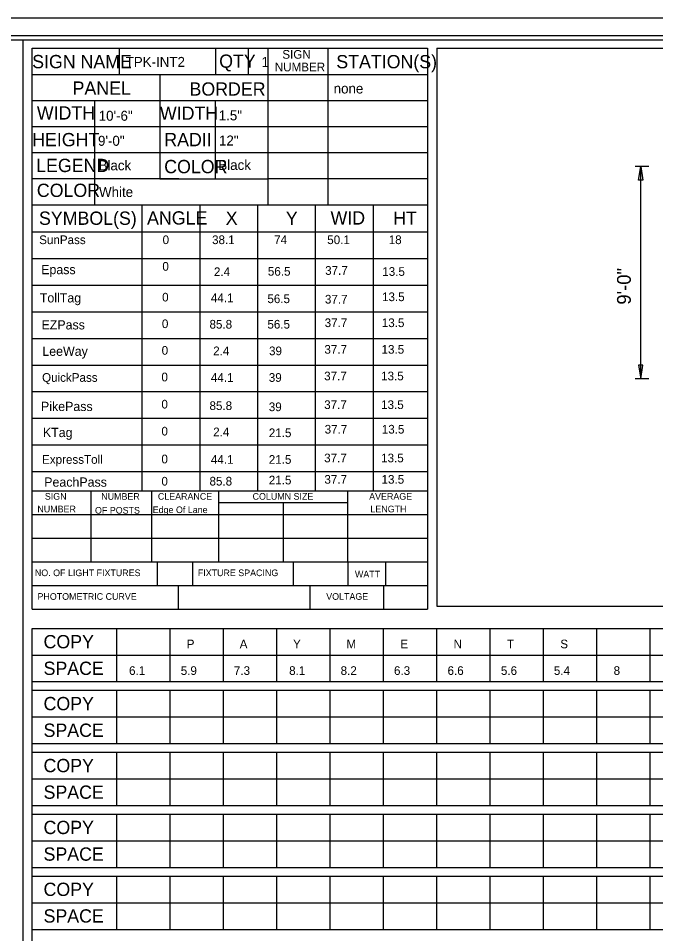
# Model space of a CAD drawing. Extents: x 17890459 to 17890580, y 17897938 to 17898017.
# Drawn here: x 17890519.38 to 17890546.34, y 17897978.61 to 17898017.37 of the extents above; entities that cross this region are included whole.
import ezdxf

# ---------------------------------------------------------------- set-up
doc = ezdxf.new("R2010")
doc.units = 0
for name, color, linetype in [('GSDims', 7, 'Continuous'), ('GSSign', 7, 'Continuous'), ('PlotBorder_dp', 7, 'Continuous'), ('SheetBorder_dp', 7, 'Continuous'), ('SheetLinesMisc2_dp', 7, 'Continuous'), ('TextMinor', 7, 'Continuous')]:
    doc.layers.add(name, color=color, linetype=linetype)

msp = doc.modelspace()

# ---------------------------------------------------------------- linework, layer by layer
at = {"layer": 'GSDims'}
for p, q in [((17890546.059, 17898011.097), (17890545.475, 17898011.097)), ((17890546.059, 17898011.097), (17890545.475, 17898011.097)), ((17890546.059, 17898011.097), (17890545.475, 17898011.097)), ((17890546.059, 17898011.097), (17890545.475, 17898011.097)), ((17890546.059, 17898011.097), (17890545.475, 17898011.097)), ((17890545.709, 17898002.097), (17890545.709, 17898011.097)), ((17890546.059, 17898002.097), (17890545.475, 17898002.097)), ((17890546.059, 17898002.097), (17890545.475, 17898002.097)), ((17890546.059, 17898002.097), (17890545.475, 17898002.097)), ((17890546.059, 17898002.097), (17890545.475, 17898002.097)), ((17890546.059, 17898002.097), (17890545.475, 17898002.097))]:
    msp.add_line(p, q, dxfattribs=at)
for points in [[(17890545.709, 17898011.097), (17890545.806, 17898010.514), (17890545.612, 17898010.514)], [(17890545.709, 17898002.097), (17890545.806, 17898002.681), (17890545.612, 17898002.681)]]:
    msp.add_lwpolyline(points, close=True, dxfattribs=at)
at = {"layer": 'PlotBorder_dp'}
msp.add_lwpolyline([(17890458.908, 17897939.544), (17890580.045, 17897939.544), (17890580.045, 17898017.365), (17890458.908, 17898017.365)], close=True, dxfattribs=at)
at = {"layer": 'SheetBorder_dp'}
msp.add_line((17890462.946, 17898016.631), (17890576.007, 17898016.631), dxfattribs=at)
at = {"layer": 'SheetLinesMisc2_dp'}
for p, q in [((17890463.151, 17898016.456), (17890575.98, 17898016.456)), ((17890463.151, 17898016.456), (17890575.98, 17898016.456)), ((17890519.566, 17898016.456), (17890519.566, 17897946.221)), ((17890519.963, 17897992.352), (17890519.963, 17898016.096)), ((17890519.963, 17898016.096), (17890536.692, 17898016.096)), ((17890523.65, 17898016.096), (17890523.65, 17898014.992)), ((17890527.717, 17898016.096), (17890527.717, 17898014.992)), ((17890529.106, 17898016.096), (17890529.106, 17898014.992)), ((17890529.934, 17898016.096), (17890529.934, 17898009.472)), ((17890532.479, 17898016.096), (17890532.479, 17898009.472)), ((17890536.692, 17898016.096), (17890536.692, 17897992.352)), ((17890537.078, 17898016.097), (17890575.452, 17898016.097)), ((17890537.078, 17898016.097), (17890537.078, 17897992.48)), ((17890519.963, 17898014.992), (17890536.692, 17898014.992)), ((17890525.369, 17898014.992), (17890525.369, 17898010.564)), ((17890519.963, 17898013.888), (17890536.692, 17898013.888)), ((17890522.606, 17898013.888), (17890522.606, 17898009.472)), ((17890527.702, 17898013.876), (17890527.702, 17898010.564)), ((17890519.963, 17898012.784), (17890536.692, 17898012.784)), ((17890519.963, 17898011.68), (17890536.692, 17898011.68)), ((17890519.963, 17898010.576), (17890526.167, 17898010.576)), ((17890525.369, 17898010.564), (17890529.934, 17898010.564)), ((17890529.934, 17898010.576), (17890536.692, 17898010.576)), ((17890519.963, 17898009.472), (17890536.692, 17898009.472)), ((17890524.608, 17898009.45), (17890524.608, 17897997.36)), ((17890527.053, 17898009.45), (17890527.053, 17897997.36)), ((17890529.497, 17898009.45), (17890529.497, 17897997.36)), ((17890531.942, 17898009.45), (17890531.942, 17897997.36)), ((17890534.386, 17898009.45), (17890534.386, 17897997.36)), ((17890519.966, 17898008.323), (17890536.692, 17898008.323)), ((17890519.966, 17898007.195), (17890536.692, 17898007.195)), ((17890519.966, 17898006.068), (17890536.692, 17898006.068)), ((17890519.966, 17898004.941), (17890536.692, 17898004.941)), ((17890519.966, 17898003.813), (17890536.692, 17898003.813)), ((17890519.966, 17898002.686), (17890536.692, 17898002.686)), ((17890519.966, 17898001.558), (17890536.692, 17898001.558)), ((17890519.966, 17898000.431), (17890536.692, 17898000.431)), ((17890519.966, 17897999.304), (17890536.692, 17897999.304)), ((17890519.966, 17897998.176), (17890536.692, 17897998.176)), ((17890519.963, 17897997.36), (17890536.692, 17897997.36)), ((17890522.445, 17897997.36), (17890522.445, 17897994.355)), ((17890525.011, 17897997.36), (17890525.011, 17897994.355)), ((17890527.844, 17897997.36), (17890527.844, 17897994.355)), ((17890533.3, 17897997.36), (17890533.3, 17897994.355)), ((17890527.844, 17897996.87), (17890533.296, 17897996.87)), ((17890530.583, 17897996.87), (17890530.583, 17897994.355)), ((17890519.963, 17897996.358), (17890536.692, 17897996.358)), ((17890519.963, 17897995.357), (17890536.692, 17897995.357)), ((17890519.963, 17897994.355), (17890536.692, 17897994.355)), ((17890525.256, 17897994.355), (17890525.256, 17897993.354)), ((17890526.751, 17897994.355), (17890526.751, 17897993.354)), ((17890531.007, 17897994.355), (17890531.007, 17897993.354)), ((17890533.322, 17897994.355), (17890533.322, 17897993.354)), ((17890534.919, 17897994.355), (17890534.919, 17897993.354)), ((17890519.963, 17897993.354), (17890536.692, 17897993.354)), ((17890526.134, 17897993.354), (17890526.134, 17897992.352)), ((17890531.716, 17897993.354), (17890531.716, 17897992.352)), ((17890534.822, 17897993.354), (17890534.822, 17897992.352)), ((17890519.963, 17897992.352), (17890536.692, 17897992.352)), ((17890537.078, 17897992.48), (17890575.452, 17897992.48)), ((17890519.957, 17897991.536), (17890575.447, 17897991.536)), ((17890519.957, 17897947.331), (17890519.957, 17897991.536)), ((17890523.529, 17897991.536), (17890523.529, 17897989.281)), ((17890525.787, 17897991.536), (17890525.787, 17897989.281)), ((17890528.044, 17897991.536), (17890528.044, 17897989.281)), ((17890530.301, 17897991.536), (17890530.301, 17897989.281)), ((17890532.558, 17897991.536), (17890532.558, 17897989.281)), ((17890534.815, 17897991.536), (17890534.815, 17897989.281)), ((17890537.073, 17897991.536), (17890537.073, 17897989.281)), ((17890539.33, 17897991.536), (17890539.33, 17897989.281)), ((17890541.587, 17897991.536), (17890541.587, 17897989.281)), ((17890543.844, 17897991.536), (17890543.844, 17897989.281)), ((17890546.102, 17897991.536), (17890546.102, 17897989.281)), ((17890519.957, 17897990.408), (17890575.447, 17897990.408)), ((17890519.957, 17897989.281), (17890575.447, 17897989.281)), ((17890519.957, 17897988.914), (17890575.447, 17897988.914)), ((17890523.529, 17897988.914), (17890523.529, 17897986.659)), ((17890525.787, 17897988.914), (17890525.787, 17897986.659)), ((17890528.044, 17897988.914), (17890528.044, 17897986.659)), ((17890530.301, 17897988.914), (17890530.301, 17897986.659)), ((17890532.558, 17897988.914), (17890532.558, 17897986.659)), ((17890534.815, 17897988.914), (17890534.815, 17897986.659)), ((17890537.073, 17897988.914), (17890537.073, 17897986.659)), ((17890539.33, 17897988.914), (17890539.33, 17897986.659)), ((17890541.587, 17897988.914), (17890541.587, 17897986.659)), ((17890543.844, 17897988.914), (17890543.844, 17897986.659)), ((17890546.102, 17897988.914), (17890546.102, 17897986.659)), ((17890519.957, 17897987.786), (17890575.447, 17897987.786)), ((17890519.957, 17897986.659), (17890575.447, 17897986.659)), ((17890519.957, 17897986.291), (17890575.447, 17897986.291)), ((17890523.529, 17897986.291), (17890523.529, 17897984.037)), ((17890525.787, 17897986.291), (17890525.787, 17897984.037)), ((17890528.044, 17897986.291), (17890528.044, 17897984.037)), ((17890530.301, 17897986.291), (17890530.301, 17897984.037)), ((17890532.558, 17897986.291), (17890532.558, 17897984.037)), ((17890534.815, 17897986.291), (17890534.815, 17897984.037)), ((17890537.073, 17897986.291), (17890537.073, 17897984.037)), ((17890539.33, 17897986.291), (17890539.33, 17897984.037)), ((17890541.587, 17897986.291), (17890541.587, 17897984.037)), ((17890543.844, 17897986.291), (17890543.844, 17897984.037)), ((17890546.102, 17897986.291), (17890546.102, 17897984.037)), ((17890519.957, 17897985.165), (17890575.447, 17897985.165)), ((17890519.957, 17897984.037), (17890575.447, 17897984.037)), ((17890519.957, 17897983.669), (17890575.447, 17897983.669)), ((17890523.529, 17897983.669), (17890523.529, 17897981.415)), ((17890525.787, 17897983.669), (17890525.787, 17897981.415)), ((17890528.044, 17897983.669), (17890528.044, 17897981.415)), ((17890530.301, 17897983.669), (17890530.301, 17897981.415)), ((17890532.558, 17897983.669), (17890532.558, 17897981.415)), ((17890534.815, 17897983.669), (17890534.815, 17897981.415)), ((17890537.073, 17897983.669), (17890537.073, 17897981.415)), ((17890539.33, 17897983.669), (17890539.33, 17897981.415)), ((17890541.587, 17897983.669), (17890541.587, 17897981.415)), ((17890543.844, 17897983.669), (17890543.844, 17897981.415)), ((17890546.102, 17897983.669), (17890546.102, 17897981.415)), ((17890519.957, 17897982.543), (17890575.447, 17897982.543)), ((17890519.957, 17897981.415), (17890575.447, 17897981.415)), ((17890519.957, 17897981.048), (17890575.447, 17897981.048)), ((17890523.529, 17897981.048), (17890523.529, 17897978.794)), ((17890525.787, 17897981.048), (17890525.787, 17897978.794)), ((17890528.044, 17897981.048), (17890528.044, 17897978.794)), ((17890530.301, 17897981.048), (17890530.301, 17897978.794)), ((17890532.558, 17897981.048), (17890532.558, 17897978.794)), ((17890534.815, 17897981.048), (17890534.815, 17897978.794)), ((17890537.073, 17897981.048), (17890537.073, 17897978.794)), ((17890539.33, 17897981.048), (17890539.33, 17897978.794)), ((17890541.587, 17897981.048), (17890541.587, 17897978.794)), ((17890543.844, 17897981.048), (17890543.844, 17897978.794)), ((17890546.102, 17897981.048), (17890546.102, 17897978.794)), ((17890519.957, 17897979.92), (17890575.447, 17897979.921)), ((17890519.957, 17897978.794), (17890575.447, 17897978.794))]:
    msp.add_line(p, q, dxfattribs=at)

# ---------------------------------------------------------------- texts
at = {"layer": 'GSDims'}
msp.add_text('9\'-0"', height=0.5833, rotation=90, dxfattribs=at).set_placement((17890545.292, 17898005.242))
at = {"layer": 'GSSign'}
for s, height, p in [('TPK-INT2', 0.4218, (17890523.919, 17898015.308)), ('1', 0.422, (17890529.666, 17898015.307)), ('none', 0.4218, (17890532.719, 17898014.182)), ('10\'-6"', 0.4218, (17890522.778, 17898013.028)), ('1.5"', 0.4218, (17890527.857, 17898013.044)), ('9\'-0"', 0.4218, (17890522.749, 17898011.968)), ('12"', 0.4218, (17890527.868, 17898011.98)), ('Black', 0.4218, (17890522.773, 17898010.928)), ('Black', 0.4218, (17890527.84, 17898010.945)), ('White', 0.4218, (17890522.792, 17898009.8)), ('SunPass', 0.3676, (17890520.26, 17898007.805)), ('0', 0.368, (17890525.482, 17898007.805)), ('38.1', 0.3676, (17890527.575, 17898007.805)), ('74', 0.3676, (17890530.2, 17898007.805)), ('50.1', 0.3676, (17890532.448, 17898007.805)), ('18', 0.3676, (17890535.049, 17898007.805)), ('Epass', 0.3921, (17890520.345, 17898006.532)), ('0', 0.368, (17890525.472, 17898006.678)), ('37.7', 0.3676, (17890532.359, 17898006.504)), ('2.4', 0.3676, (17890527.652, 17898006.451)), ('56.5', 0.3676, (17890529.936, 17898006.468)), ('13.5', 0.3676, (17890534.776, 17898006.461)), ('TollTag', 0.3921, (17890520.287, 17898005.335)), ('0', 0.368, (17890525.462, 17898005.376)), ('44.1', 0.3676, (17890527.524, 17898005.347)), ('13.5', 0.3676, (17890534.766, 17898005.391)), ('56.5', 0.3676, (17890529.916, 17898005.307)), ('37.7', 0.3676, (17890532.349, 17898005.288)), ('EZPass', 0.3921, (17890520.358, 17898004.193)), ('0', 0.368, (17890525.452, 17898004.249)), ('85.8', 0.3676, (17890527.466, 17898004.228)), ('56.5', 0.3676, (17890529.916, 17898004.228)), ('37.7', 0.3676, (17890532.339, 17898004.292)), ('13.5', 0.3676, (17890534.756, 17898004.292)), ('LeeWay', 0.3921, (17890520.393, 17898003.074)), ('0', 0.368, (17890525.442, 17898003.122)), ('2.4', 0.3676, (17890527.622, 17898003.101)), ('39', 0.3676, (17890529.985, 17898003.101)), ('37.7', 0.3676, (17890532.329, 17898003.165)), ('13.5', 0.3676, (17890534.746, 17898003.165)), ('QuickPass', 0.3676, (17890520.382, 17898001.975)), ('0', 0.368, (17890525.432, 17898001.994)), ('44.1', 0.3676, (17890527.524, 17898001.974)), ('39', 0.3676, (17890529.975, 17898001.974)), ('37.7', 0.3676, (17890532.318, 17898002.038)), ('13.5', 0.3676, (17890534.727, 17898002.038)), ('PikePass', 0.3921, (17890520.336, 17898000.738)), ('0', 0.368, (17890525.432, 17898000.844)), ('85.8', 0.3676, (17890527.466, 17898000.781)), ('39', 0.3676, (17890529.975, 17898000.733)), ('37.7', 0.3676, (17890532.318, 17898000.823)), ('13.5', 0.3676, (17890534.727, 17898000.823)), ('KTag', 0.3921, (17890520.417, 17897999.635)), ('0', 0.368, (17890525.432, 17897999.702)), ('2.4', 0.3676, (17890527.622, 17897999.669)), ('21.5', 0.3676, (17890529.975, 17897999.632)), ('37.7', 0.3676, (17890532.339, 17897999.783)), ('13.5', 0.3676, (17890534.756, 17897999.783)), ('ExpressToll', 0.36762, (17890520.382, 17897998.504)), ('0', 0.368, (17890525.432, 17897998.523)), ('44.1', 0.3676, (17890527.524, 17897998.503)), ('21.5', 0.3676, (17890529.975, 17897998.503)), ('37.7', 0.3676, (17890532.318, 17897998.567)), ('13.5', 0.3676, (17890534.727, 17897998.567)), ('PeachPass', 0.3921, (17890520.473, 17897997.534)), ('0', 0.368, (17890525.432, 17897997.582)), ('85.8', 0.3676, (17890527.466, 17897997.584)), ('21.5', 0.3676, (17890529.975, 17897997.632)), ('37.7', 0.3676, (17890532.329, 17897997.661)), ('13.5', 0.3676, (17890534.746, 17897997.661)), ('P', 0.368, (17890526.503, 17897990.692)), ('A', 0.368, (17890528.744, 17897990.692)), ('Y', 0.368, (17890531.001, 17897990.692)), ('M', 0.368, (17890533.259, 17897990.692)), ('E', 0.368, (17890535.543, 17897990.692)), ('N', 0.368, (17890537.792, 17897990.692)), ('T', 0.368, (17890540.05, 17897990.692)), ('S', 0.368, (17890542.308, 17897990.692)), ('6.1', 0.3676, (17890524.062, 17897989.565)), ('5.9', 0.3676, (17890526.249, 17897989.565)), ('7.3', 0.3676, (17890528.498, 17897989.565)), ('8.1', 0.3676, (17890530.835, 17897989.565)), ('8.2', 0.3676, (17890533.014, 17897989.565)), ('6.3', 0.3676, (17890535.272, 17897989.565)), ('6.6', 0.3676, (17890537.538, 17897989.565)), ('5.6', 0.3676, (17890539.796, 17897989.565)), ('5.4', 0.3676, (17890542.036, 17897989.565)), ('8', 0.368, (17890544.565, 17897989.565))]:
    msp.add_text(s, height=height, dxfattribs=at).set_placement(p)
at = {"layer": 'TextMinor'}
for s, height, p in [('SIGN NAME', 0.5624, (17890519.963, 17898015.251)), ('QTY', 0.5624, (17890527.877, 17898015.27)), ('SIGN', 0.3676, (17890530.548, 17898015.654)), ('STATION(S)', 0.5624, (17890532.831, 17898015.248)), ('NUMBER', 0.3676, (17890530.228, 17898015.119)), ('PANEL', 0.5624, (17890521.673, 17898014.129)), ('BORDER', 0.5624, (17890526.62, 17898014.091)), ('WIDTH', 0.5624, (17890520.161, 17898013.079)), ('WIDTH', 0.5624, (17890525.369, 17898013.067)), ('HEIGHT', 0.5624, (17890519.963, 17898011.947)), ('RADII', 0.5624, (17890525.554, 17898011.949)), ('LEGEND', 0.5624, (17890520.132, 17898010.855)), ('COLOR', 0.5624, (17890525.55, 17898010.807)), ('COLOR', 0.5624, (17890520.161, 17898009.801)), ('SYMBOL(S)', 0.5624, (17890520.251, 17898008.621)), ('ANGLE', 0.5624, (17890524.824, 17898008.633)), ('X', 0.562, (17890528.153, 17898008.621)), ('Y', 0.562, (17890530.695, 17898008.621)), ('WID', 0.5624, (17890532.587, 17898008.633)), ('HT', 0.5624, (17890535.237, 17898008.622)), ('SIGN', 0.2812, (17890520.499, 17897996.984)), ('NUMBER', 0.2812, (17890522.886, 17897996.981)), ('CLEARANCE', 0.2812, (17890525.281, 17897996.983)), ('COLUMN SIZE', 0.28123, (17890529.289, 17897996.983)), ('AVERAGE', 0.2812, (17890534.221, 17897996.983)), ('NUMBER', 0.2812, (17890520.184, 17897996.449)), ('OF POSTS', 0.2812, (17890522.621, 17897996.396)), ('Edge Of Lane', 0.28123, (17890525.064, 17897996.417)), ('LENGTH', 0.2812, (17890534.275, 17897996.449)), ('NO. OF LIGHT FIXTURES', 0.28114, (17890520.078, 17897993.748)), ('FIXTURE SPACING', 0.28114, (17890526.971, 17897993.748)), ('WATT', 0.2811, (17890533.62, 17897993.692)), ('PHOTOMETRIC CURVE', 0.28114, (17890520.188, 17897992.746)), ('VOLTAGE', 0.2811, (17890532.405, 17897992.746)), ('COPY', 0.5625, (17890520.444, 17897990.692)), ('SPACE', 0.5625, (17890520.444, 17897989.565)), ('COPY', 0.5625, (17890520.444, 17897988.071)), ('SPACE', 0.5625, (17890520.444, 17897986.943)), ('COPY', 0.5625, (17890520.444, 17897985.448)), ('SPACE', 0.5625, (17890520.444, 17897984.321)), ('COPY', 0.5625, (17890520.444, 17897982.827)), ('SPACE', 0.5625, (17890520.444, 17897981.7)), ('COPY', 0.5625, (17890520.444, 17897980.207)), ('SPACE', 0.5625, (17890520.444, 17897979.08))]:
    msp.add_text(s, height=height, dxfattribs=at).set_placement(p)

doc.saveas('drawing.dxf')
